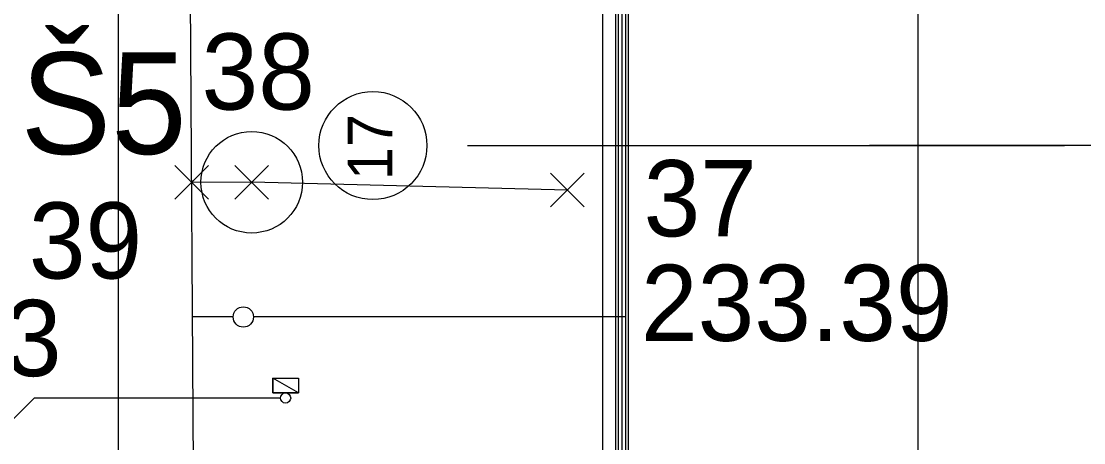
# Model space of a CAD drawing. Extents: x -264031 to -263588, y -1242281 to -1242059.
# Drawn here: x -263926.05 to -263905.12, y -1242194.73 to -1242186.43 of the extents above; entities that cross this region are included whole.
import ezdxf

# ---------------------------------------------------------------- set-up
doc = ezdxf.new("R2010")
doc.units = 0
for name, color, linetype in [('HESCON_OSI_STAVBY_KFA', 7, 'Continuous'), ('KFA_2D_SITUACIA_DSP', 7, 'Continuous'), ('KFA_BODY_CISLO', 7, 'Continuous'), ('KFA_BODY_SYMBOL', 7, 'Continuous'), ('KFA_BODY_VYSKA', 7, 'Continuous'), ('KFA_JESTV_IS_DSP_-_KANAL_SPLASK', 7, 'Continuous'), ('KFA_SO-40-1-II_SK_MER_TRIBUNA_A', 7, 'Continuous'), ('POPIS', 7, 'Continuous')]:
    doc.layers.add(name, color=color, linetype=linetype)

msp = doc.modelspace()

# ---------------------------------------------------------------- linework, layer by layer
at = {"layer": 'HESCON_OSI_STAVBY_KFA'}
for p, q in [((-263908.393, -1242083.237), (-263908.393, -1242246.707)), ((-263917.265, -1242188.882), (-263905.505, -1242188.882)), ((-263917.265, -1242188.882), (-263905.505, -1242188.882)), ((-263792.653, -1242188.882), (-263909.343, -1242188.882))]:
    msp.add_line(p, q, dxfattribs=at)
msp.add_circle((-263919.125, -1242188.882), 1.064, dxfattribs=at)
at = {"layer": 'KFA_2D_SITUACIA_DSP'}
for p, q in [((-263914.218, -1242196.332), (-263914.218, -1242132.432)), ((-263924.143, -1242185.14), (-263924.143, -1242250.14)), ((-263921.877, -1242192.257), (-263922.677, -1242192.257)), ((-263915.293, -1242192.257), (-263921.477, -1242192.257)), ((-263914.143, -1242192.257), (-263915.293, -1242192.257)), ((-263921.093, -1242193.752), (-263921.093, -1242193.462)), ((-263921.093, -1242193.462), (-263920.593, -1242193.462)), ((-263920.593, -1242193.752), (-263921.093, -1242193.462)), ((-263920.593, -1242193.752), (-263921.093, -1242193.462)), ((-263921.093, -1242193.462), (-263921.093, -1242193.752)), ((-263920.593, -1242193.462), (-263920.593, -1242193.752)), ((-263925.798, -1242193.852), (-263926.593, -1242194.648)), ((-263920.944, -1242193.852), (-263925.798, -1242193.852)), ((-263920.593, -1242193.752), (-263921.093, -1242193.752)), ((-263921.093, -1242193.752), (-263920.593, -1242193.752))]:
    msp.add_line(p, q, dxfattribs=at)
for points in [[(-263794.893, -1242227.382), (-263808.968, -1242241.457), (-263894.968, -1242241.457), (-263909.043, -1242227.382), (-263909.043, -1242196.333), (-263914.143, -1242196.333), (-263914.143, -1242132.433), (-263909.043, -1242132.433), (-263909.043, -1242101.382), (-263894.968, -1242087.307), (-263808.968, -1242087.307), (-263794.893, -1242101.382), (-263794.893, -1242227.382)], [(-263918.489, -1242164.132), (-263914.1, -1242168.521), (-263914.1, -1242199.486), (-263910.004, -1242203.582), (-263891.768, -1242203.582)], [(-263918.593, -1242164.382), (-263914.35, -1242168.625), (-263914.35, -1242199.59), (-263910.108, -1242203.832), (-263891.768, -1242203.832)], [(-263918.696, -1242164.632), (-263914.6, -1242168.728), (-263914.6, -1242199.693), (-263910.211, -1242204.082), (-263891.768, -1242204.082)]]:
    msp.add_lwpolyline(points, dxfattribs=at)
msp.add_lwpolyline([(-263893.618, -1242118.282), (-263916.093, -1242118.282), (-263916.093, -1242175.482), (-263914.293, -1242175.482), (-263914.293, -1242210.482), (-263893.618, -1242210.482), (-263893.618, -1242166.382), (-263900.043, -1242166.382), (-263900.043, -1242162.382), (-263893.618, -1242162.382)], close=True, dxfattribs=at)
for centre, radius in [((-263921.677, -1242192.257), 0.2), ((-263920.844, -1242193.852), 0.1)]:
    msp.add_circle(centre, radius, dxfattribs=at)
at = {"layer": 'KFA_BODY_SYMBOL'}
for p, q in [((-263923.026, -1242189.938), (-263922.363, -1242189.275)), ((-263922.363, -1242189.938), (-263923.026, -1242189.275)), ((-263921.843, -1242189.936), (-263921.18, -1242189.272)), ((-263921.18, -1242189.936), (-263921.843, -1242189.272)), ((-263915.625, -1242190.089), (-263914.962, -1242189.426)), ((-263914.962, -1242190.089), (-263915.625, -1242189.426))]:
    msp.add_line(p, q, dxfattribs=at)
at = {"layer": 'KFA_JESTV_IS_DSP_-_KANAL_SPLASK'}
msp.add_line((-263922.479, -1242221.753), (-263922.731, -1242184.174), dxfattribs=at)
at = {"layer": 'KFA_SO-40-1-II_SK_MER_TRIBUNA_A'}
msp.add_lwpolyline([(-263915.293, -1242189.757), (-263921.511, -1242189.604), (-263922.694, -1242189.607)], dxfattribs=at)
msp.add_circle((-263921.511, -1242189.604), 1, dxfattribs=at)

# ---------------------------------------------------------------- texts
at = {"layer": 'HESCON_OSI_STAVBY_KFA'}
msp.add_text('17', height=0.875, rotation=90, dxfattribs=at).set_placement((-263918.744, -1242189.562))
at = {"layer": 'KFA_BODY_CISLO'}
for s, p in [('38', (-263922.499, -1242188.175)), ('37', (-263913.793, -1242190.669)), ('39', (-263925.901, -1242191.5))]:
    msp.add_text(s, height=1.5, dxfattribs=at).set_placement(p)
at = {"layer": 'KFA_BODY_VYSKA'}
for s, p in [('233.39', (-263913.845, -1242192.728)), ('233.23', (-263931.392, -1242193.421))]:
    msp.add_text(s, height=1.5, dxfattribs=at).set_placement(p)
at = {"layer": 'POPIS'}
msp.add_text('Š5', height=2, dxfattribs=at).set_placement((-263926.064, -1242189.047))

doc.saveas('drawing.dxf')
